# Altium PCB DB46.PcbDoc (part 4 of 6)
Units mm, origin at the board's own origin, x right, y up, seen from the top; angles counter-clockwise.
Board outline 82.2 x 113.2 mm, 8 copper layers (Top Layer, MidLayer1, MidLayer2, GND, MidLayer3, VCC, MidLayer4, Bottom Layer), stack 1.576 mm thick; 186 components, 477 nets, 1727 pads, 1538 vias.
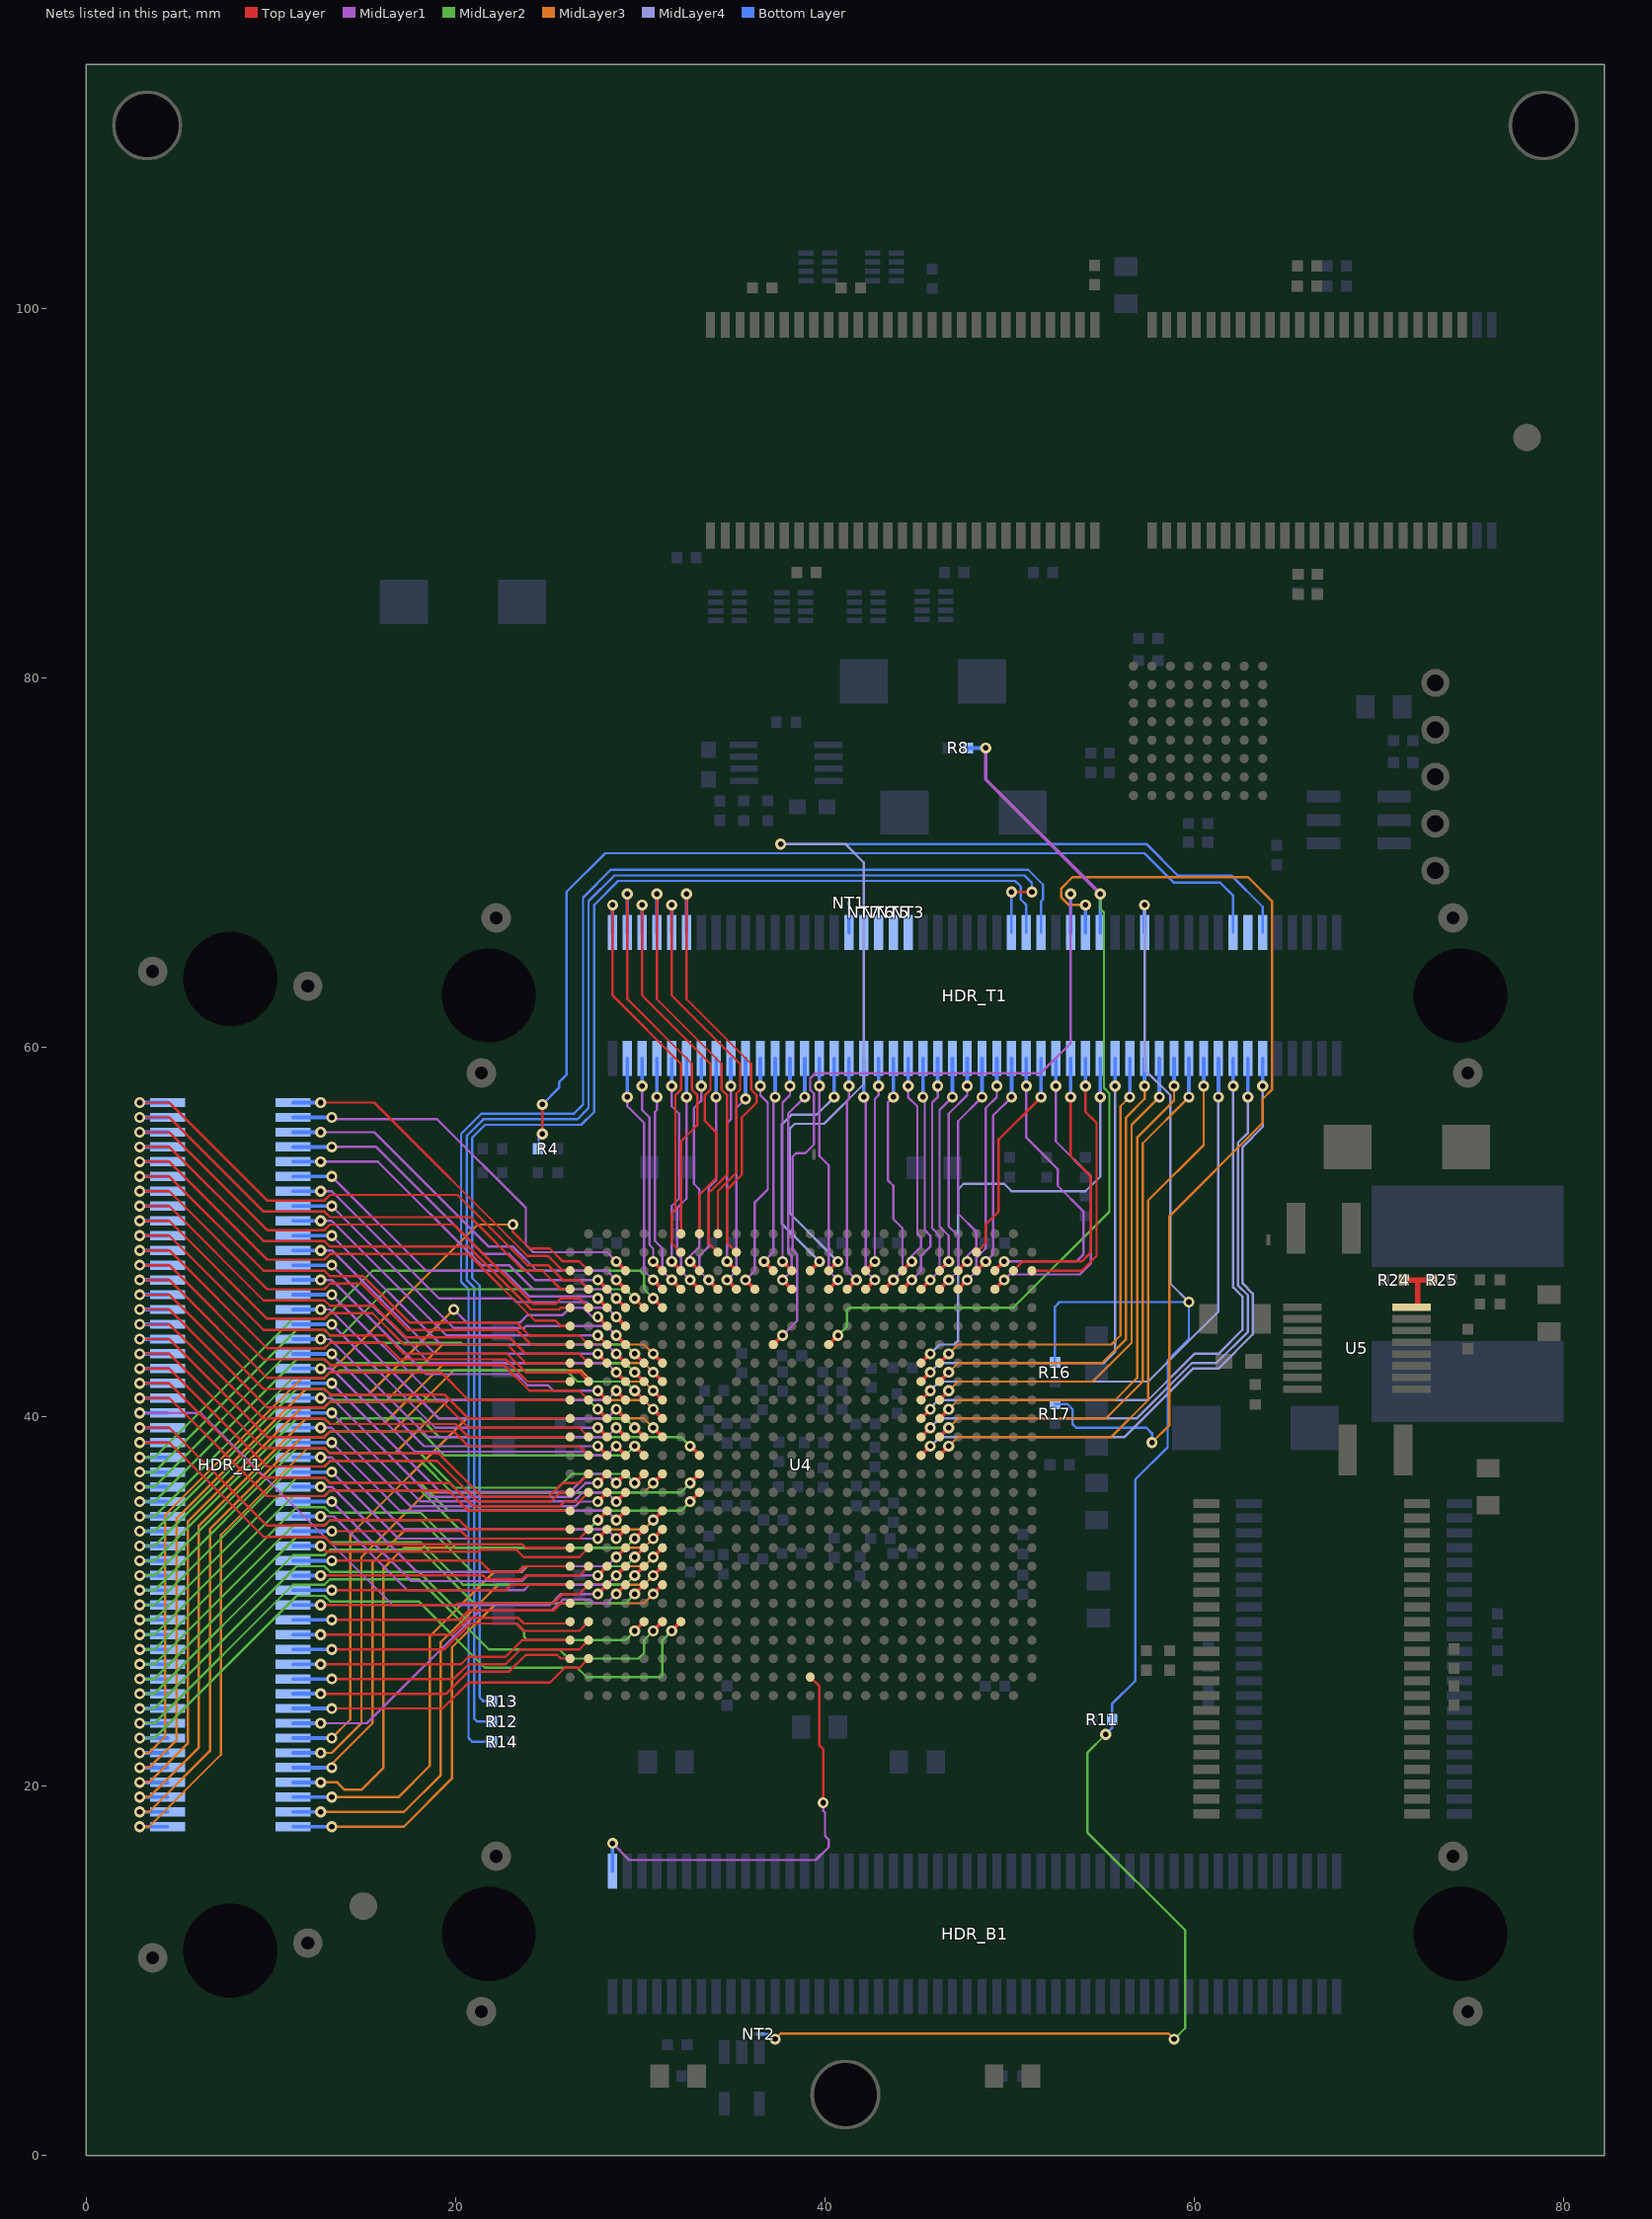
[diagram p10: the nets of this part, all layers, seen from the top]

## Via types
v1: diameter 0.6, hole 0.3, Top Layer to Bottom Layer, 904 vias
v2: diameter 0.6, hole 0.3, Top Layer to Bottom Layer, tented both sides, 506 vias
v3: diameter 0.7, hole 0.4, Top Layer to Bottom Layer, 127 vias
v4: diameter 0.6, hole 0.3, Top Layer to Bottom Layer, tented top, 1 vias

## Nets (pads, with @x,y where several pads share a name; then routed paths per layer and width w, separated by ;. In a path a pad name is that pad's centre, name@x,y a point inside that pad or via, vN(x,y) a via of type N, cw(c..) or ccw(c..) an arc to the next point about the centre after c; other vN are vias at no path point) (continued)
EXTEND_A0: HDR_L1.1 U4.D2 | length 30.2
  Top Layer w0.127: v2(2.9,57) 4.5,57 9.8,51.7 12.9,51.7 13.2,52 20.1,52 23.9,48.2 24.3,48.2 24.6,48.2 25,48.2 25.8,47.4 26.7,47.4 U4.D2@27.2,46.9
  Bottom Layer w0.2: v2(2.9,57) HDR_L1.1@4.4,57
EXTEND_A1: HDR_L1.3 U4.D1 | length 29.1
  Top Layer w0.127: v2(2.9,56.2) 3.9,56.2 ; 3.5,56.2 4.5,56.2 9.6,51.1 12.9,51.1 13.2,50.8 20.8,50.8 23.7,47.9 24.3,47.9 24.6,47.9 24.7,47.9 25.7,46.9 U4.D1@26.2,46.9
  Bottom Layer w0.2: v2(2.9,56.2) HDR_L1.3@4.4,56.2
EXTEND_A2: HDR_L1.5 U4.E2 | length 30.7
  Top Layer w0.127: v2(2.9,55.4) 4,55.4 ; 3.5,55.4 4.5,55.4 9.8,50.1 12.9,50.1 13.2,50.4 19.9,50.4 24.2,46.1 24.3,46.1 24.6,46.1 25.4,46.1 25.7,46.4 26.7,46.4 U4.E2@27.2,45.9
  Bottom Layer w0.2: v2(2.9,55.4) HDR_L1.5@4.4,55.4
EXTEND_A3: HDR_L1.7 U4.E1 | length 28.9
  Top Layer w0.127: v2(2.9,54.6) 3.9,54.6 ; 3.5,54.6 4.5,54.6 9.6,49.5 12.9,49.5 13.2,49.2 20.7,49.2 24.1,45.8 24.3,45.8 24.6,45.8 25.6,45.8 25.7,45.9 U4.E1@26.2,45.9
  Bottom Layer w0.2: v2(2.9,54.6) HDR_L1.7@4.4,54.6
EXTEND_A4: HDR_L1.9 U4.F1 | length 29
  Top Layer w0.127: v2(2.9,53.8) 3.8,53.8 ; 3.5,53.8 4.5,53.8 9.8,48.5 12.9,48.5 13.2,48.8 20.7,48.8 24.3,45.2 24.6,45.2 25.4,45.2 25.7,44.9 U4.F1@26.2,44.9
  Bottom Layer w0.2: v2(2.9,53.8) HDR_L1.9@4.4,53.8
EXTEND_A5: HDR_L1.11 U4.G2 | length 29.9
  Top Layer w0.127: v2(2.9,53) 3.8,53 ; 3.5,53 4.5,53 9.6,47.9 12.9,47.9 13.2,47.6 15,47.6 17.5,45.1 23.3,45.1 23.5,44.9 24,44.4 25.8,44.4 26.7,44.4 U4.G2@27.2,43.9
  Bottom Layer w0.2: v2(2.9,53) HDR_L1.11@4.4,53
EXTEND_A6: HDR_L1.13 U4.G1 | length 28.8
  Top Layer w0.127: v2(2.9,52.2) 3.8,52.2 ; 3.5,52.2 4.5,52.2 9.8,46.9 12.9,46.9 13.2,47.2 14.9,47.2 17.4,44.7 23.3,44.7 24.1,43.9 24.3,43.9 24.6,43.9 U4.G1@26.2,43.9
  Bottom Layer w0.2: v2(2.9,52.2) HDR_L1.13@4.4,52.2
EXTEND_A7: HDR_L1.15 U4.H2 | length 29.6
  Top Layer w0.127: v2(2.9,51.4) 3.8,51.4 ; 3.5,51.4 4.5,51.4 9.6,46.3 12.9,46.3 13.2,46 15.6,46 17.3,44.3 22.9,44.3 23.8,43.4 24.3,43.4 24.6,43.4 26.7,43.4 U4.H2@27.2,42.9
  Bottom Layer w0.2: v2(2.9,51.4) HDR_L1.15@4.4,51.4
EXTEND_A8: HDR_L1.17 U4.H1 | length 28.5
  Top Layer w0.127: v2(2.9,50.6) 3.8,50.6 ; 3.5,50.6 4.5,50.6 9.8,45.3 12.9,45.3 13.2,45.6 15.5,45.6 17.2,43.9 22.8,43.9 23.8,42.9 24.3,42.9 24.6,42.9 U4.H1@26.2,42.9
  Bottom Layer w0.2: v2(2.9,50.6) HDR_L1.17@4.4,50.6
EXTEND_A9: HDR_L1.19 U4.J2 | length 29.4
  Top Layer w0.127: v2(2.9,49.8) 3.8,49.8 ; 3.5,49.8 4.5,49.8 9.6,44.7 12.9,44.7 13.2,44.4 16.2,44.4 17.2,43.4 22.8,43.4 23.8,42.4 24.3,42.4 24.6,42.4 26.7,42.4 U4.J2@27.2,41.9
  Bottom Layer w0.2: v2(2.9,49.8) HDR_L1.19@4.4,49.8
EXTEND_A10: HDR_L1.21 U4.J1 | length 28.3
  Top Layer w0.127: v2(2.9,49) 3.8,49 ; 3.5,49 4.5,49 9.8,43.7 12.9,43.7 13.2,44 16.1,44 17,43.1 22.7,43.1 23.9,41.9 24.3,41.9 24.6,41.9 U4.J1@26.2,41.9
  Bottom Layer w0.2: v2(2.9,49) HDR_L1.21@4.4,49
EXTEND_A11: HDR_L1.23 U4.K2 | length 29.1
  Top Layer w0.127: v2(2.9,48.2) 3.8,48.2 ; 3.5,48.2 4.5,48.2 9.6,43.1 12.9,43.1 13.2,42.8 22.6,42.8 24,41.4 24.3,41.4 24.6,41.4 26.7,41.4 U4.K2@27.2,40.9
  Bottom Layer w0.2: v2(2.9,48.2) HDR_L1.23@4.4,48.2
EXTEND_A12: HDR_L1.25 U4.K1 | length 27.7
  Top Layer w0.127: v2(2.9,47.4) 4.5,47.4 9.8,42.1 12.9,42.1 13.2,42.4 19.2,42.4 20.7,40.9 24.3,40.9 24.6,40.9 U4.K1@26.2,40.9
  Bottom Layer w0.2: v2(2.9,47.4) HDR_L1.25@4.4,47.4
EXTEND_A13: HDR_L1.27 U4.L1 | length 27.6
  Top Layer w0.127: v2(2.9,46.6) 4.5,46.6 9.6,41.5 12.9,41.5 13.2,41.2 19.4,41.2 20.7,39.9 24.3,39.9 24.6,39.9 U4.L1@26.2,39.9
  Bottom Layer w0.2: v2(2.9,46.6) HDR_L1.27@4.4,46.6
EXTEND_A14: HDR_L1.29 U4.M2 | length 28.9
  Top Layer w0.127: v2(2.9,45.8) 4.5,45.8 9.8,40.5 12.9,40.5 13.2,40.8 19.3,40.8 20.7,39.4 24.3,39.4 24.6,39.4 26.7,39.4 U4.M2@27.2,38.9
  Bottom Layer w0.2: v2(2.9,45.8) HDR_L1.29@4.4,45.8
EXTEND_A15: HDR_L1.31 U4.M1 | length 27.3
  Top Layer w0.127: v2(2.9,45) 4.5,45 9.6,39.9 12.9,39.9 13.2,39.6 20,39.6 20.7,38.9 24.3,38.9 24.6,38.9 U4.M1@26.2,38.9
  Bottom Layer w0.2: v2(2.9,45) HDR_L1.31@4.4,45
EXTEND_A16: HDR_L1.33 U4.N2 | length 28.7
  Top Layer w0.127: v2(2.9,44.2) 4.5,44.2 9.8,38.9 12.9,38.9 13.2,39.2 19.9,39.2 20.7,38.4 24.3,38.4 24.6,38.4 26.7,38.4 U4.N2@27.2,37.9
  Bottom Layer w0.2: v2(2.9,44.2) HDR_L1.33@4.4,44.2
EXTEND_A17: HDR_L1.35 U4.P2 | length 29.5
  Top Layer w0.127: v2(2.9,43.4) 4.5,43.4 9.6,38.3 12.9,38.3 13.2,38 19.1,38 21.438,35.662 25.046,35.662 25.784,36.4 26.7,36.4 U4.P2@27.2,36.9
  Bottom Layer w0.2: v2(2.9,43.4) HDR_L1.35@4.4,43.4
EXTEND_A18: HDR_L1.37 U4.R1 | length 28.2
  Top Layer w0.127: v2(2.9,42.6) 4.5,42.6 9.8,37.3 12.9,37.3 13.2,37.6 19,37.6 20.7,35.9 21.192,35.408 25.151,35.408 25.643,35.9 U4.R1@26.2,35.9
  Bottom Layer w0.2: v2(2.9,42.6) HDR_L1.37@4.4,42.6
EXTEND_A19: HDR_L1.39 U4.R2 | length 28.9
  Top Layer w0.127: v2(2.9,41.8) 4.5,41.8 9.6,36.7 12.9,36.7 13.2,36.4 19.7,36.4 20.946,35.154 25.654,35.154 25.9,35.4 26.7,35.4 U4.R2@27.2,35.9
  Bottom Layer w0.2: v2(2.9,41.8) HDR_L1.39@4.4,41.8
EXTEND_A20: HDR_L1.41 U4.T1 | length 27.6
  Top Layer w0.127: v2(2.9,41) 4.5,41 9.8,35.7 12.9,35.7 13.2,36 19.6,36 20.7,34.9 24.3,34.9 24.6,34.9 U4.T1@26.2,34.9
  Bottom Layer w0.2: v2(2.9,41) HDR_L1.41@4.4,41
EXTEND_A21: HDR_L1.43 U4.Y3 | length 31.6
  Top Layer w0.2: v1(27.7,30.4) U4.Y3@28.2,30.9
  MidLayer1 w0.127: v2(2.9,40.2) 6.2,40.2 16.6,29.8 24.3,29.8 24.6,29.8 25.1,29.8 25.7,30.4 v1(27.7,30.4)
  Bottom Layer w0.2: v2(2.9,40.2) HDR_L1.43@4.4,40.2
EXTEND_A22: HDR_L1.45 U4.U1 | length 27.3
  Top Layer w0.127: v2(2.9,39.4) 4.5,39.4 9.8,34.1 12.9,34.1 13.2,34.4 20.2,34.4 20.7,33.9 24.3,33.9 24.6,33.9 U4.U1@26.2,33.9
  Bottom Layer w0.2: v2(2.9,39.4) HDR_L1.45@4.4,39.4
EXTEND_A23: HDR_L1.47 U4.V1 | length 27.5
  Top Layer w0.127: v2(2.9,38.6) 3.8,38.6 ; 3.5,38.6 4.5,38.6 9.6,33.5 12.9,33.5 13.3,33.1 23.6,33.1 23.8,32.9 24.3,32.9 24.6,32.9 U4.V1@26.2,32.9
  Bottom Layer w0.2: v2(2.9,38.6) HDR_L1.47@4.4,38.6
EXTEND_A24: HDR_L1.49 U4.E6 | length 35.3
  Top Layer w0.2: v1(30.7,46.4) U4.E6@31.2,45.9
  MidLayer2 w0.127: v2(2.9,37.8) 3.7,37.8 11.2,45.3 12.9,45.3 14,46.4 15.5,47.9 24.3,47.9 24.6,47.9 30,47.9 30.2,47.7 30.2,46.9 v1(30.7,46.4)
  Bottom Layer w0.2: v2(2.9,37.8) HDR_L1.49@4.4,37.8
EXTEND_A25: HDR_L1.51 U4.E5 | length 33.6
  Top Layer w0.2: v1(29.7,46.4) U4.E5@30.2,45.9
  MidLayer2 w0.127: v2(2.9,37) 3.7,37 11.4,44.7 12.9,44.7 13.2,44.4 13.8,44.4 15.4,46 16.3,46.9 24.3,46.9 24.6,46.9 29.2,46.9 v1(29.7,46.4)
  Bottom Layer w0.2: v2(2.9,37) HDR_L1.51@4.4,37
EXTEND_A26: HDR_L1.53 U4.H5 | length 32.5
  Top Layer w0.2: v1(29.7,43.4) U4.H5@30.2,42.9
  MidLayer2 w0.127: v2(2.9,36.2) 3.7,36.2 11.2,43.7 12.9,43.7 13.2,44 20.3,44 20.4,43.9 24.3,43.9 24.6,43.9 29.2,43.9 v1(29.7,43.4)
  Bottom Layer w0.2: v2(2.9,36.2) HDR_L1.53@4.4,36.2
EXTEND_A27: HDR_L1.55 U4.J5 | length 32.6
  Top Layer w0.2: v1(29.7,42.4) U4.J5@30.2,41.9
  MidLayer2 w0.127: v2(2.9,35.4) 3.7,35.4 11.4,43.1 12.9,43.1 13.2,42.8 13.5,42.8 13.6,42.9 24.3,42.9 24.6,42.9 29.2,42.9 v1(29.7,42.4)
  Bottom Layer w0.2: v2(2.9,35.4) HDR_L1.55@4.4,35.4
EXTEND_A28: HDR_L1.57 U4.K5 | length 32.7
  Top Layer w0.2: v1(29.7,41.4) U4.K5@30.2,40.9
  MidLayer2 w0.127: v2(2.9,34.6) 3.7,34.6 11.2,42.1 12.9,42.1 13.2,42.4 13.6,42.4 13.7,42.5 24.3,42.5 24.6,42.5 26,42.5 26.6,41.9 29.2,41.9 v1(29.7,41.4)
  Bottom Layer w0.2: v2(2.9,34.6) HDR_L1.57@4.4,34.6
EXTEND_A29: HDR_L1.59 U4.L3 | length 30.8
  Top Layer w0.2: v1(27.7,40.4) U4.L3@28.2,39.9
  MidLayer2 w0.127: v2(2.9,33.8) 3.7,33.8 11.4,41.5 12.9,41.5 13.2,41.2 18.2,41.2 18.5,40.9 24.3,40.9 24.6,40.9 27.2,40.9 v1(27.7,40.4)
  Bottom Layer w0.2: v2(2.9,33.8) HDR_L1.59@4.4,33.8
  Bottom Layer w0.381: v1(27.7,40.4) v1@27.7,40.508
EXTEND_A30: HDR_L1.61 U4.M5 | length 32.9
  Top Layer w0.2: v1(29.7,39.4) U4.M5@30.2,38.9
  MidLayer2 w0.127: v2(2.9,33) 3.7,33 11.2,40.5 12.9,40.5 13.3,40.9 18.1,40.9 19.1,39.9 24.3,39.9 24.6,39.9 29.2,39.9 v1(29.7,39.4)
  Bottom Layer w0.2: v2(2.9,33) HDR_L1.61@4.4,33
EXTEND_A31: HDR_L1.63 U4.N8 | length 36.1
  Top Layer w0.2: v1@32.7,38.475 32.737,38.432 U4.N8@33.2,37.9
  MidLayer2 w0.127: v2(2.9,32.2) 3.7,32.2 11.4,39.9 12.9,39.9 13.2,39.6 13.5,39.6 13.8,39.9 18.1,39.9 19.1,38.9 24.3,38.9 24.6,38.9 32.2,38.9 v1(32.7,38.4)
  Bottom Layer w0.2: v2(2.9,32.2) HDR_L1.63@4.4,32.2
EXTEND_A32: HDR_L1.65 U4.N5 | length 33
  Top Layer w0.2: v1(29.7,38.4) U4.N5@30.2,37.9
  MidLayer2 w0.127: v2(2.9,31.4) 3.7,31.4 11.2,38.9 12.9,38.9 13.2,39.2 18.1,39.2 19.4,37.9 24.3,37.9 24.6,37.9 29.2,37.9 v1(29.7,38.4)
  Bottom Layer w0.2: v2(2.9,31.4) HDR_L1.65@4.4,31.4
EXTEND_A33: HDR_L1.67 U4.P5 | length 33.6
  Top Layer w0.2: v1(29.7,36.4) U4.P5@30.2,36.9
  MidLayer2 w0.127: v2(2.9,30.6) 3.7,30.6 11.4,38.3 12.9,38.3 13.2,38 18.1,38 19.946,36.154 25.554,36.154 26.3,36.9 29.2,36.9 v1(29.7,36.4)
  Bottom Layer w0.2: v2(2.9,30.6) HDR_L1.67@4.4,30.6
EXTEND_A34: HDR_L1.69 U4.P8 | length 36.1
  Top Layer w0.2: v1(32.7,36.4) U4.P8@33.2,36.9
  MidLayer2 w0.127: v2(2.9,29.8) 3.7,29.8 11.2,37.3 12.9,37.3 13.2,37.6 18.1,37.6 19.8,35.9 24.3,35.9 24.6,35.9 32.2,35.9 v1(32.7,36.4)
  Bottom Layer w0.2: v2(2.9,29.8) HDR_L1.69@4.4,29.8
EXTEND_A35: HDR_L1.71 U4.R8 | length 36.1
  Top Layer w0.2: v1(32.7,35.4) U4.R8@33.2,35.9
  MidLayer2 w0.127: v2(2.9,29) 3.7,29 11.4,36.7 12.9,36.7 13.2,36.4 18.1,36.4 19.6,34.9 24.3,34.9 24.6,34.9 32.2,34.9 v1(32.7,35.4)
  Bottom Layer w0.2: v2(2.9,29) HDR_L1.71@4.4,29
EXTEND_A36: HDR_L1.73 U4.T3 | length 31.4
  Top Layer w0.2: v1(27.7,34.4) U4.T3@28.2,34.9
  MidLayer2 w0.127: v2(2.9,28.2) 3.7,28.2 11.2,35.7 12.9,35.7 13.2,36 18.1,36 20.2,33.9 24.3,33.9 24.6,33.9 27.2,33.9 v1(27.7,34.4)
  Bottom Layer w0.2: v2(2.9,28.2) HDR_L1.73@4.4,28.2
  Bottom Layer w0.381: v1(27.7,34.4) v1@27.7,34.508
EXTEND_A37: HDR_L1.75 U4.U5 | length 33.3
  Top Layer w0.2: v1(29.7,33.4) U4.U5@30.2,33.9
  MidLayer2 w0.127: v2(2.9,27.4) 3.7,27.4 11.4,35.1 12.9,35.1 13.2,34.8 18.1,34.8 20,32.9 24.3,32.9 24.6,32.9 29.2,32.9 v1(29.7,33.4)
  Bottom Layer w0.2: v2(2.9,27.4) HDR_L1.75@4.4,27.4
EXTEND_A38: HDR_L1.77 U4.V5 | length 33.7
  Top Layer w0.2: v1(29.7,32.4) U4.V5@30.2,32.9
  MidLayer2 w0.127: v2(2.9,26.6) 3.7,26.6 11.2,34.1 12.9,34.1 13.2,34.4 18.1,34.4 20.9,31.6 23.4,31.6 23.7,31.9 24.3,31.9 24.6,31.9 29.2,31.9 v1(29.7,32.4)
  Bottom Layer w0.2: v2(2.9,26.6) HDR_L1.77@4.4,26.6
EXTEND_A39: HDR_L1.79 U4.W5 | length 33.5
  Top Layer w0.2: v1(29.7,31.4) U4.W5@30.2,31.9
  MidLayer2 w0.127: v2(2.9,25.8) 3.7,25.8 11.4,33.5 12.9,33.5 13.2,33.2 18.1,33.2 20.4,30.9 24.3,30.9 24.6,30.9 29.2,30.9 v1(29.7,31.4)
  Bottom Layer w0.2: v2(2.9,25.8) HDR_L1.79@4.4,25.8
EXTEND_A40: HDR_L1.81 U4.Y5 | length 33.6
  Top Layer w0.2: v1(29.7,30.4) U4.Y5@30.2,30.9
  MidLayer2 w0.127: v2(2.9,25) 3.7,25 11.2,32.5 12.9,32.5 13.2,32.8 18.1,32.8 21,29.9 24.3,29.9 24.6,29.9 29.2,29.9 v1(29.7,30.4)
  Bottom Layer w0.2: v2(2.9,25) HDR_L1.81@4.4,25
EXTEND_A41: HDR_L1.83 U4.AB5 | length 34.2
  Top Layer w0.2: v1(29.7,28.4) U4.AB5@30.2,28.9
  MidLayer2 w0.127: v2(2.9,24.2) 3.7,24.2 11.4,31.9 12.9,31.9 13.2,31.6 18,31.6 20.8,28.8 23.3,28.8 23.7,28.4 23.7,28.1 23.9,27.9 24.3,27.9 24.6,27.9 29.2,27.9 v1(29.7,28.4)
  Bottom Layer w0.2: v2(2.9,24.2) HDR_L1.83@4.4,24.2
EXTEND_A42: HDR_L1.85 U4.AB6 | length 36.1
  Top Layer w0.2: v1(30.7,28.4) U4.AB6@31.2,28.9
  MidLayer2 w0.127: v2(2.9,23.4) 3.7,23.4 11.2,30.9 12.9,30.9 13.2,31.2 18,31.2 21.8,27.4 24.3,27.4 24.6,27.4 25.625,27.4 26.125,26.9 29.9,26.9 30.2,27.2 30.2,27.9 v1(30.7,28.4)
  Bottom Layer w0.2: v2(2.9,23.4) HDR_L1.85@4.4,23.4
EXTEND_A43: HDR_L1.87 U4.AB7 | length 38.2
  Top Layer w0.2: v1(31.7,28.4) U4.AB7@32.2,28.9
  MidLayer2 w0.127: v2(2.9,22.6) 3.7,22.6 11.4,30.3 12.9,30.3 13.2,30 18,30 21.6,26.4 24.3,26.4 24.6,26.4 26.6,26.4 27.1,25.9 31.1,25.9 31.2,26 31.2,27.9 v1(31.7,28.4)
  Bottom Layer w0.2: v2(2.9,22.6) HDR_L1.87@4.4,22.6
EXTEND_A44: HDR_L1.89 U4.C2 | length 45.9
  Top Layer w0.127: v1(23.1,50.4) 23.1,50 24,49.1 24.3,49.1 24.6,49.1 25.1,49.1 25.8,48.4 26.7,48.4 U4.C2@27.2,47.9
  MidLayer3 w0.127: v2(2.9,21.8) 3.4,21.8 4.277,22.677 4.277,34.677 11.7,42.1 12.9,42.1 21.2,50.4 v1(23.1,50.4)
  Bottom Layer w0.2: v2(2.9,21.8) HDR_L1.89@4.4,21.8
EXTEND_A45: HDR_L1.91 U4.F3 | length 45.4
  Top Layer w0.2: v1(27.7,45.4) U4.F3@28.2,44.9
  MidLayer1 w0.127: v1(19.9,45.8) 20.6,45.1 23.5,45.1 23.9,45.5 24.3,45.5 24.6,45.5 25.8,45.5 26.2,45.9 26.9,45.9 27.4,45.4 v1(27.7,45.4)
  MidLayer3 w0.127: v2(2.9,21) 3.4,21 4.9,22.5 4.9,34.5 11.9,41.5 12.9,41.5 13.2,41.2 15.3,41.2 v1(19.9,45.8)
  Bottom Layer w0.2: v2(2.9,21) HDR_L1.91@4.4,21
EXTEND_A46: HDR_L1.93 U4.H6 | length 47.1
  Top Layer w0.2: v1(30.7,43.4) U4.H6@31.2,42.9
  MidLayer3 w0.127: v2(2.9,20.2) 3.4,20.2 5.5,22.3 5.5,34.3 11.7,40.5 12.9,40.5 13.2,40.8 16.2,40.8 19.3,43.9 24.3,43.9 24.6,43.9 30.2,43.9 v1(30.7,43.4)
  Bottom Layer w0.2: v2(2.9,20.2) HDR_L1.93@4.4,20.2
EXTEND_A47: HDR_L1.95 U4.J6 | length 47.2
  Top Layer w0.2: v1(30.7,42.4) U4.J6@31.2,41.9
  MidLayer3 w0.127: v2(2.9,19.4) 3.4,19.4 6.1,22.1 6.1,34.1 11.9,39.9 12.9,39.9 13.2,39.6 16.1,39.6 19.4,42.9 24.3,42.9 24.6,42.9 30.2,42.9 v1(30.7,42.4)
  Bottom Layer w0.2: v2@2.9,19.4 HDR_L1.95@4.4,19.4
EXTEND_A48: HDR_L1.97 U4.K6 | length 47.4
  Top Layer w0.2: v1(30.7,41.4) U4.K6@31.2,40.9
  MidLayer3 w0.127: v2(2.9,18.6) 3.4,18.6 6.7,21.9 6.7,33.9 11.7,38.9 12.912,38.9 12.912,38.912 13.2,39.2 16.6,39.2 19.9,42.5 24.3,42.5 24.6,42.5 26.8,42.5 27.4,41.9 30.2,41.9 v1(30.7,41.4)
  Bottom Layer w0.2: v2(2.9,18.6) HDR_L1.97@4.4,18.6
EXTEND_A49: HDR_L1.99 U4.L6 | length 47
  Top Layer w0.2: v1(30.7,40.4) U4.L6@31.2,39.9
  MidLayer3 w0.127: v2(2.9,17.8) 3.4,17.8 7.3,21.7 7.3,33.6 12,38.3 12.9,38.3 13.2,38 16.7,38 19.6,40.9 24.3,40.9 24.6,40.9 30.2,40.9 v1(30.7,40.4)
  Bottom Layer w0.2: v2(2.9,17.8) HDR_L1.99@4.4,17.8
EXTEND_B0: HDR_L1.2 U4.C1 | length 18.8
  Top Layer w0.127: v2(12.7,57) 15.6,57 23.9,48.7 24.3,48.7 24.6,48.7 25,48.7 25.8,47.9 U4.C1@26.2,47.9
  Bottom Layer w0.2: HDR_L1.2@11.2,57 v2(12.7,57)
EXTEND_B1: HDR_L1.4 U4.C4 | length 22.6
  Top Layer w0.2: v1(28.7,48.4) U4.C4@29.2,47.9
  MidLayer1 w0.127: v2(13.3,56.2) 13.4,56.2 13.5,56.1 19,56.1 23.8,51.3 23.8,49.3 24.2,48.9 28.2,48.9 v1(28.7,48.4)
  Bottom Layer w0.2: HDR_L1.4@11.2,56.2 v2(13.3,56.2)
EXTEND_B2: HDR_L1.6 U4.D4 | length 21.5
  Top Layer w0.2: v1(28.7,47.4) U4.D4@29.2,46.9
  MidLayer1 w0.127: v2(12.7,55.4) 15.6,55.4 21.8,49.2 23.1,49.2 24.4,47.9 28.2,47.9 v1(28.7,47.4)
  Bottom Layer w0.2: HDR_L1.6@11.2,55.4 v2(12.7,55.4)
EXTEND_B3: HDR_L1.8 U4.D3 | length 20.2
  Top Layer w0.2: v1(27.7,47.4) U4.D3@28.2,46.9
  MidLayer1 w0.127: v2(13.3,54.6) 15.7,54.6 21.5,48.8 22.9,48.8 24.3,47.4 v1(27.7,47.4)
  Bottom Layer w0.2: HDR_L1.8@11.2,54.6 v2(13.3,54.6)
EXTEND_B4: HDR_L1.10 U4.E4 | length 21.3
  Top Layer w0.2: v1(28.7,46.4) U4.E4@29.2,45.9
  MidLayer1 w0.127: v2(12.7,53.8) 15.8,53.8 21.4,48.2 22.9,48.2 24.2,46.9 28.2,46.9 v1(28.7,46.4)
  Bottom Layer w0.2: HDR_L1.10@11.2,53.8 v2(12.7,53.8)
EXTEND_B5: HDR_L1.12 U4.E3 | length 19.9
  Top Layer w0.2: v1(27.7,46.4) U4.E3@28.2,45.9
  MidLayer1 w0.127: v2(13.3,53) 18.4,47.9 22.6,47.9 24,46.5 27.6,46.5 v1(27.7,46.4)
  Bottom Layer w0.2: HDR_L1.12@11.2,53 v2(13.3,53)
EXTEND_B6: HDR_L1.14 U4.F4 | length 21
  Top Layer w0.2: v1(28.7,45.4) U4.F4@29.2,44.9
  MidLayer1 w0.127: v2(12.7,52.2) 13.3,52.2 19.1,46.4 23.1,46.4 23.3,46.2 24.3,46.2 24.6,46.2 27.1,46.2 27.4,45.9 28.2,45.9 v1(28.7,45.4)
  Bottom Layer w0.2: HDR_L1.14@11.2,52.2 v2(12.7,52.2)
EXTEND_B7: HDR_L1.16 U4.G4 | length 21.2
  Top Layer w0.2: v1(28.7,44.4) U4.G4@29.2,43.9
  MidLayer1 w0.127: v2(13.3,51.4) 19.9,44.8 23.7,44.8 23.8,44.9 24.3,44.9 24.6,44.9 28.2,44.9 v1(28.7,44.4)
  Bottom Layer w0.2: HDR_L1.16@11.2,51.4 v2(13.3,51.4)
EXTEND_B8: HDR_L1.18 U4.G3 | length 19.8
  Top Layer w0.127: v1(27.7,44.4) U4.G3@28.2,43.9
  MidLayer1 w0.127: v2(12.7,50.6) 13.3,50.6 19.5,44.4 24.3,44.4 24.6,44.4 v1(27.7,44.4)
  Bottom Layer w0.2: HDR_L1.18@11.2,50.6 v2(12.7,50.6)
EXTEND_B9: HDR_L1.20 U4.H4 | length 23.8
  Top Layer w0.2: v1(28.7,43.4) U4.H4@29.2,42.9
  MidLayer1 w0.127: v2(13.3,49.8) 19.2,43.9 24.3,43.9 24.6,43.9 28.2,43.9 ; 25.3,43.9 28.2,43.9 ; v1(28.7,43.4) 28.2,43.9
  Bottom Layer w0.2: HDR_L1.20@11.2,49.8 v2(13.3,49.8)
EXTEND_B10: HDR_L1.22 U4.H3 | length 19.5
  Top Layer w0.2: v1(27.7,43.4) U4.H3@28.2,42.9
  MidLayer1 w0.127: v2(12.7,49) 13.3,49 18.9,43.4 24.3,43.4 24.6,43.4 v1(27.7,43.4)
  Bottom Layer w0.2: HDR_L1.22@11.2,49 v2(12.7,49)
EXTEND_B11: HDR_L1.24 U4.J4 | length 20.6
  Top Layer w0.2: v1(28.7,42.4) U4.J4@29.2,41.9
  MidLayer1 w0.127: v2(13.3,48.2) 18.6,42.9 24.3,42.9 24.6,42.9 28.2,42.9 v1(28.7,42.4)
  Bottom Layer w0.2: HDR_L1.24@11.2,48.2 v2(13.3,48.2)
EXTEND_B12: HDR_L1.26 U4.K3 | length 19.7
  Top Layer w0.2: v1(27.7,41.4) U4.K3@28.2,40.9
  MidLayer1 w0.127: v2(12.7,47.4) 13.3,47.4 18.4,42.3 23.3,42.3 23.9,41.7 24.3,41.7 24.6,41.7 25,41.7 25.3,41.4 v1(27.7,41.4)
  Bottom Layer w0.2: HDR_L1.26@11.2,47.4 v2(12.7,47.4)
EXTEND_B13: HDR_L1.28 U4.K4 | length 20.8
  Top Layer w0.2: v1(28.7,41.4) U4.K4@29.2,40.9
  MidLayer1 w0.127: v2(13.3,46.6) 19,40.9 24.3,40.9 24.6,40.9 25.3,40.9 28.2,40.9 v1(28.7,41.4)
  Bottom Layer w0.2: HDR_L1.28@11.2,46.6 v2(13.3,46.6)
EXTEND_B14: HDR_L1.30 U4.L4 | length 20.9
  Top Layer w0.2: v1(28.7,40.4) U4.L4@29.2,39.9
  MidLayer1 w0.127: v2(12.7,45.8) 13.2,45.8 19.1,39.9 24.3,39.9 24.6,39.9 28.2,39.9 v1(28.7,40.4)
  Bottom Layer w0.2: HDR_L1.30@11.2,45.8 v2(12.7,45.8)
EXTEND_B15: HDR_L1.32 U4.M3 | length 19.5
  Top Layer w0.2: v1(27.7,39.4) U4.M3@28.2,38.9
  MidLayer1 w0.127: v2(13.3,45) 18.9,39.4 24.3,39.4 24.6,39.4 v1(27.7,39.4)
  Bottom Layer w0.2: HDR_L1.32@11.2,45 v2(13.3,45)
EXTEND_B16: HDR_L1.34 U4.M4 | length 20.6
  Top Layer w0.2: v1(28.7,39.4) U4.M4@29.2,38.9
  MidLayer1 w0.127: v2(12.7,44.2) 13.2,44.2 18.5,38.9 24.3,38.9 24.6,38.9 28.2,38.9 v1(28.7,39.4)
  Bottom Layer w0.2: HDR_L1.34@11.2,44.2 v2(12.7,44.2)
EXTEND_B17: HDR_L1.36 U4.N3 | length 19.3
  Top Layer w0.2: v1(27.7,38.4) U4.N3@28.2,37.9
  MidLayer1 w0.127: v2(13.3,43.4) 18.3,38.4 24.3,38.4 24.6,38.4 v1(27.7,38.4)
  Bottom Layer w0.2: HDR_L1.36@11.2,43.4 v2(13.3,43.4)
EXTEND_B18: HDR_L1.38 U4.N4 | length 20.4
  Top Layer w0.2: v1(28.7,38.4) U4.N4@29.2,37.9
  MidLayer1 w0.127: v2(12.7,42.6) 13.3,42.6 17.8,38.1 24.3,38.1 24.6,38.1 27.2,38.1 27.4,37.9 28.2,37.9 v1(28.7,38.4)
  Bottom Layer w0.2: HDR_L1.38@11.2,42.6 v2(12.7,42.6)
EXTEND_B19: HDR_L1.40 U4.P4 | length 21.3
  Top Layer w0.2: v1(28.7,36.4) U4.P4@29.2,36.9
  MidLayer1 w0.127: v2(13.3,41.8) 19.184,35.916 26.184,35.916 27.168,36.9 28.2,36.9 v1(28.7,36.4)
  Bottom Layer w0.2: HDR_L1.40@11.2,41.8 v2(13.3,41.8)
EXTEND_B20: HDR_L1.42 U4.P3 | length 19.7
  Top Layer w0.2: v1(27.7,36.4) U4.P3@28.2,36.9
  MidLayer1 w0.127: v2(12.7,41) 13.3,41 18.638,35.662 26.29,35.662 27.027,36.4 v1(27.7,36.4)
  Bottom Layer w0.2: HDR_L1.42@11.2,41 v2(12.7,41)
EXTEND_B21: HDR_L1.44 U4.R4 | length 20.6
  Top Layer w0.2: v1(28.7,35.4) U4.R4@29.2,35.9
  MidLayer1 w0.127: v2(13.3,40.2) 18.092,35.408 26.395,35.408 26.887,35.9 28.2,35.9 v1(28.7,35.4)
  Bottom Layer w0.2: HDR_L1.44@11.2,40.2 v2(13.3,40.2)
EXTEND_B22: HDR_L1.46 U4.R3 | length 19.1
  Top Layer w0.2: v1(27.7,35.4) U4.R3@28.2,35.9
  MidLayer1 w0.127: v2(12.7,39.4) 13.3,39.4 17.546,35.154 26.5,35.154 26.746,35.4 v1(27.7,35.4)
  Bottom Layer w0.2: HDR_L1.46@11.2,39.4 v2(12.7,39.4)
EXTEND_B23: HDR_L1.48 U4.T4 | length 19.9
  Top Layer w0.2: v1(28.7,34.4) U4.T4@29.2,34.9
  MidLayer1 w0.127: v2(13.3,38.6) 17,34.9 24.3,34.9 24.6,34.9 28.2,34.9 v1(28.7,34.4)
  Bottom Layer w0.2: HDR_L1.48@11.2,38.6 v2(13.3,38.6)
EXTEND_B24: HDR_L1.50 U4.U4 | length 20
  Top Layer w0.2: v1(28.7,33.4) U4.U4@29.2,33.9
  MidLayer1 w0.127: v2(12.7,37.8) 13.3,37.8 17.2,33.9 24.3,33.9 24.6,33.9 25.3,33.9 28.2,33.9 v1(28.7,33.4)
  Bottom Layer w0.2: HDR_L1.50@11.2,37.8 v2(12.7,37.8)
EXTEND_B25: HDR_L1.52 U4.U3 | length 18.7
  Top Layer w0.2: v1(27.7,33.4) U4.U3@28.2,33.9
  MidLayer1 w0.127: v2(13.3,37) 16.9,33.4 24.3,33.4 24.6,33.4 25.3,33.4 v1(27.7,33.4)
  Bottom Layer w0.2: HDR_L1.52@11.2,37 v2(13.3,37)
EXTEND_B26: HDR_L1.54 U4.V4 | length 20.4
  Top Layer w0.2: v1(28.7,32.4) U4.V4@29.2,32.9
  MidLayer1 w0.127: v2(12.7,36.2) 13.3,36.2 17.9,31.6 23.5,31.6 23.8,31.9 24.3,31.9 24.6,31.9 28.2,31.9 v1(28.7,32.4)
  Bottom Layer w0.2: HDR_L1.54@11.2,36.2 v2(12.7,36.2)
EXTEND_B27: HDR_L1.56 U4.W3 | length 19.1
  Top Layer w0.2: v1(27.7,31.4) U4.W3@28.2,31.9
  MidLayer1 w0.127: v2(13.3,35.4) 17.6,31.1 23.6,31.1 23.9,31.4 24.3,31.4 24.6,31.4 v1(27.7,31.4)
  Bottom Layer w0.2: HDR_L1.56@11.2,35.4 v2(13.3,35.4)
EXTEND_B28: HDR_L1.58 U4.W4 | length 23.1
  Top Layer w0.2: v1(28.7,31.4) U4.W4@29.2,31.9
  MidLayer1 w0.127: v2(12.7,34.6) 13.4,34.6 17.4,30.6 23.7,30.6 24,30.9 24.3,30.9 24.6,30.9 28.2,30.9 ; 25.3,30.9 28.2,30.9 ; v1(28.7,31.4) 28.2,30.9
  Bottom Layer w0.2: HDR_L1.58@11.2,34.6 v2(12.7,34.6)
EXTEND_B29: HDR_L1.60 U4.U2 | length 16.4
  Top Layer w0.127: v2(13.3,33.8) 20.3,33.8 20.7,33.4 24.3,33.4 24.6,33.4 26.7,33.4 U4.U2@27.2,33.9
  Bottom Layer w0.2: HDR_L1.60@11.2,33.8 v2(13.3,33.8)
EXTEND_B30: HDR_L1.62 U4.V2 | length 16.5
  Top Layer w0.127: v2(12.7,33) 13,32.7 21.3,32.7 21.4,32.8 23.3,32.8 23.7,32.4 24.3,32.4 24.6,32.4 26.7,32.4 U4.V2@27.2,32.9
  Bottom Layer w0.2: HDR_L1.62@11.2,33 v2(12.7,33)
EXTEND_B31: HDR_L1.64 U4.W1 | length 15.4
  Top Layer w0.127: v2(13.3,32.2) 21.3,32.2 21.9,31.6 23.4,31.6 23.7,31.9 24.3,31.9 24.6,31.9 U4.W1@26.2,31.9
  Bottom Layer w0.2: HDR_L1.64@11.2,32.2 v2(13.3,32.2)
EXTEND_B32: HDR_L1.66 U4.W2 | length 16.4
  Top Layer w0.127: v2(12.7,31.4) 21.5,31.4 21.7,31.2 23.6,31.2 23.8,31.4 24.3,31.4 24.6,31.4 26.7,31.4 U4.W2@27.2,31.9
  Bottom Layer w0.2: HDR_L1.66@11.2,31.4 v2(12.7,31.4)
EXTEND_B33: HDR_L1.68 U4.Y1 | length 15.1
  Top Layer w0.127: v2(13.3,30.6) 22.7,30.6 23,30.9 24.3,30.9 24.6,30.9 U4.Y1@26.2,30.9
  Bottom Layer w0.2: HDR_L1.68@11.2,30.6 v2(13.3,30.6)
EXTEND_B34: HDR_L1.70 U4.Y2 | length 16.5
  Top Layer w0.127: v2(12.7,29.8) 20,29.8 20.1,29.9 24.3,29.9 24.6,29.9 25.3,29.9 25.8,30.4 26.7,30.4 U4.Y2@27.2,30.9
  Bottom Layer w0.2: HDR_L1.70@11.2,29.8 v2(12.7,29.8)
EXTEND_B35: HDR_L1.72 U4.AA1 | length 15.4
  Top Layer w0.127: v2(13.3,29) 20.2,29 20.7,29.5 24.3,29.5 24.6,29.5 25.3,29.5 25.7,29.9 U4.AA1@26.2,29.9
  Bottom Layer w0.2: HDR_L1.72@11.2,29 v2(13.3,29)
EXTEND_B36: HDR_L1.74 U4.AB1 | length 15.5
  Top Layer w0.127: v2(12.7,28.2) 19.8,28.2 20.7,29.1 23.4,29.1 23.7,28.8 24.3,28.8 24.6,28.8 26.1,28.8 U4.AB1@26.2,28.9
  Bottom Layer w0.2: HDR_L1.74@11.2,28.2 v2(12.7,28.2)
EXTEND_B37: HDR_L1.76 U4.AB2 | length 17
  Top Layer w0.127: v2(13.3,27.4) 19.4,27.4 20.8,28.8 23.3,28.8 23.7,28.4 24.3,28.4 24.6,28.4 25.7,28.4 26.7,28.4 U4.AB2@27.2,28.9
  Bottom Layer w0.2: HDR_L1.76@11.2,27.4 v2(13.3,27.4)
EXTEND_B38: HDR_L1.78 U4.AC1 | length 15.5
  Top Layer w0.127: v2(12.7,26.6) 20.3,26.6 20.7,27 22.7,27 23.6,27.9 24.3,27.9 24.6,27.9 U4.AC1@26.2,27.9
  Bottom Layer w0.2: HDR_L1.78@11.2,26.6 v2(12.7,26.6)
EXTEND_B39: HDR_L1.80 U4.AC2 | length 16.9
  Top Layer w0.127: v2(13.3,25.8) 19.9,25.8 20.7,26.6 22.7,26.6 23.5,27.4 24.3,27.4 24.6,27.4 26.7,27.4 U4.AC2@27.2,27.9
  Bottom Layer w0.2: HDR_L1.80@11.2,25.8 v2(13.3,25.8)
EXTEND_B40: HDR_L1.82 U4.AD1 | length 16
  Top Layer w0.127: v2(12.7,25) 19.5,25 20.7,26.2 22.9,26.2 23.8,27.1 24.3,27.1 24.6,27.1 25.5,27.1 25.7,26.9 U4.AD1@26.2,26.9
  Bottom Layer w0.2: HDR_L1.82@11.2,25 v2(12.7,25)
EXTEND_B41: HDR_L1.84 U4.AD2 | length 17.1
  Top Layer w0.127: v2(13.3,24.2) 19.3,24.2 20.7,25.6 24.3,25.6 24.6,25.6 25.1,25.6 25.9,26.4 26.7,26.4 U4.AD2@27.2,26.9
  Bottom Layer w0.2: HDR_L1.84@11.2,24.2 v2(13.3,24.2)
EXTEND_B42: HDR_L1.86 U4.Y4 | length 21.3
  Top Layer w0.2: v1(28.7,30.4) U4.Y4@29.2,30.9
  MidLayer1 w0.127: v2(12.7,23.4) 15.2,23.4 21.3,29.5 24.3,29.5 24.6,29.5 25.2,29.5 25.8,30.1 27.3,30.1 27.5,29.9 28.2,29.9 v1(28.7,30.4)
  Bottom Layer w0.2: HDR_L1.86@11.2,23.4 v2(12.7,23.4)
EXTEND_B43: HDR_L1.88 U4.M6 | length 33.4
  Top Layer w0.2: v1(30.7,39.4) U4.M6@31.2,38.9
  MidLayer3 w0.127: v2(13.3,22.6) 14.3,23.6 14.3,33.6 20.6,39.9 24.3,39.9 24.6,39.9 26.4,39.9 30.2,39.9 v1(30.7,39.4)
  Bottom Layer w0.2: HDR_L1.88@11.2,22.6 v2(13.3,22.6)
EXTEND_B44: HDR_L1.90 U4.P6 | length 31.5
  Top Layer w0.2: v1(30.7,36.4) U4.P6@31.2,36.9
  MidLayer3 w0.127: v2(12.7,21.8) 13.3,21.8 14.9,23.4 14.9,32.4 18.4,35.9 24.3,35.9 24.6,35.9 30.2,35.9 v1(30.7,36.4)
  Bottom Layer w0.2: HDR_L1.90@11.2,21.8 v2(12.7,21.8)
EXTEND_B45: HDR_L1.92 U4.T6 | length 31
  Top Layer w0.2: v1(30.7,34.4) U4.T6@31.2,34.9
  MidLayer3 w0.127: v2(13.3,21) 13.3,21.2 15.5,23.4 15.5,32.1 17.3,33.9 24.3,33.9 24.6,33.9 30.2,33.9 v1(30.7,34.4)
  Bottom Layer w0.2: HDR_L1.92@11.2,21 v2(13.3,21)
EXTEND_B46: HDR_L1.94 U4.U6 | length 32.3
  Top Layer w0.2: v1(30.7,33.4) U4.U6@31.2,33.9
  MidLayer3 w0.127: v2(12.7,20.2) 13.6,20.2 14,19.8 14.9,19.8 16.1,21 16.1,31.8 17.2,32.9 24.3,32.9 24.6,32.9 30.2,32.9 v1(30.7,33.4)
  Bottom Layer w0.2: HDR_L1.94@11.2,20.2 v2(12.7,20.2)
EXTEND_B47: HDR_L1.96 U4.V6 | length 29.7
  Top Layer w0.2: v1(30.7,32.4) U4.V6@31.2,32.9
  MidLayer3 w0.127: v2(13.3,19.4) 16.9,19.4 18.6,21.1 18.6,28.1 22.1,31.6 23.6,31.6 23.9,31.9 24.3,31.9 24.6,31.9 30.2,31.9 v1(30.7,32.4)
  Bottom Layer w0.2: HDR_L1.96@11.2,19.4 v2(13.3,19.4)
EXTEND_B48: HDR_L1.98 U4.W6 | length 29.7
  Top Layer w0.2: v1(30.7,31.4) U4.W6@31.2,31.9
  MidLayer3 w0.127: v2(12.7,18.6) 17.2,18.6 19.2,20.6 19.2,27.8 22.3,30.9 24.3,30.9 24.6,30.9 30.2,30.9 v1(30.7,31.4)
  Bottom Layer w0.2: HDR_L1.98@11.2,18.6 v2(12.7,18.6)
EXTEND_B49: HDR_L1.100 U4.Y6 | length 29.6
  Top Layer w0.2: v1(30.7,30.4) U4.Y6@31.2,30.9
  MidLayer3 w0.127: v2(13.3,17.8) 17.2,17.8 19.8,20.4 19.8,27.5 22.2,29.9 24.3,29.9 24.6,29.9 30.2,29.9 v1(30.7,30.4)
  Bottom Layer w0.2: HDR_L1.100@11.2,17.8 v2(13.3,17.8)
EXTEND_C0: HDR_T1.89 U4.N20 | length 37.8
  Top Layer w0.178: U4.N20@45.2,37.9 v1(45.7,38.4)
  MidLayer4 w0.127: v1@45.75,38.4 46.2,38.9 52.8,38.9 53.1,38.9 56.218,38.9 59.918,42.6 61.3,42.6 63.154,44.454 63.154,46.664 62.608,47.21 62.608,54.597 63.7,55.689 v2(63.7,57.9)
  Bottom Layer w0.2: v2(63.7,57.9) HDR_T1.89@63.7,59.4 v2(63.7,57.9)
EXTEND_C1: HDR_T1.87 U4.M20 | length 35.3
  Top Layer w0.178: U4.M20@45.2,38.9 v1(45.7,39.4)
  MidLayer4 w0.127: v1(45.7,39.4) 46.2,39.9 52.8,39.9 53.1,39.9 56.859,39.9 59.859,42.9 61.2,42.9 62.9,44.6 62.9,46.559 62.354,47.105 62.354,54.826 62.9,55.372 v2(62.9,57.3)
  Bottom Layer w0.2: v2(62.9,57.3) HDR_T1.87@62.9,59.4
EXTEND_C2: HDR_T1.85 U4.L20 | length 34.3
  Top Layer w0.178: U4.L20@45.2,39.9 v1(45.7,40.4)
  MidLayer4 w0.127: v1(45.7,40.4) 46.1,40.9 50,40.9 52.8,40.9 53.1,40.9 57.5,40.9 60,43.4 61.3,43.4 62.6,44.7 62.6,46.5 62.1,47 v2(62.1,57.9)
  Bottom Layer w0.2: v2(62.1,57.9) HDR_T1.85@62.1,59.4
EXTEND_C3: HDR_T1.83 U4.K20 | length 31.8
  Top Layer w0.178: U4.K20@45.2,40.9 v1(45.7,41.4)
  MidLayer4 w0.127: v1(45.7,41.4) 46.2,41.9 52.8,41.9 53.1,41.9 57.5,41.9 60.879,45.279 61.3,45.7 v2(61.3,57.3)
  Bottom Layer w0.2: v2(61.3,57.3) HDR_T1.83@61.3,59.4
EXTEND_C4: HDR_T1.81 U4.N21 | length 32.3
  Top Layer w0.2: U4.N21@46.2,37.9 v1(46.7,38.4)
  MidLayer3 w0.127: v1(46.7,38.4) 47.2,38.9 52.8,38.9 53.1,38.9 55.5,38.9 57.5,40.9 57.5,51.7 60.5,54.7 v2(60.5,57.9)
  Bottom Layer w0.2: v2(60.5,57.9) HDR_T1.81@60.5,59.4
EXTEND_C5: HDR_T1.79 U4.M21 | length 30.8
  Top Layer w0.2: U4.M21@46.2,38.9 v1(46.7,39.4)
  MidLayer3 w0.127: v1(46.7,39.4) 47.2,39.9 51,39.9 52.8,39.9 53.1,39.9 55.2,39.9 57.2,41.9 57.2,54.8 v2(59.7,57.3)
  Bottom Layer w0.2: v2(59.7,57.3) HDR_T1.79@59.7,59.4
EXTEND_C6: HDR_T1.77 U4.L21 | length 29.7
  Top Layer w0.2: U4.L21@46.2,39.9 v1(46.7,40.4)
  MidLayer3 w0.127: v1(46.7,40.4) 47.2,40.9 52.8,40.9 53.1,40.9 55.7,40.9 56.9,42.1 56.9,55.1 58.9,57.1 v2(58.9,57.9)
  Bottom Layer w0.2: v2(58.9,57.9) HDR_T1.77@58.9,59.4
EXTEND_C7: HDR_T1.75 U4.K21 | length 27.7
  Top Layer w0.2: U4.K21@46.2,40.9 v1(46.7,41.4)
  MidLayer3 w0.127: v1(46.7,41.4) 47.2,41.9 52.8,41.9 53.1,41.9 54.5,41.9 56.6,44 56.6,55.8 v2(58.1,57.3)
  Bottom Layer w0.2: v2(58.1,57.3) HDR_T1.75@58.1,59.4
EXTEND_C8: HDR_T1.73 U4.J21 | length 26.7
  Top Layer w0.2: U4.J21@46.2,41.9 v1(46.7,42.4)
  MidLayer3 w0.127: v1(46.7,42.4) 47.2,42.9 52.8,42.9 53.1,42.9 55,42.9 56.3,44.2 56.3,56.2 57.3,57.2 v2(57.3,57.9)
  Bottom Layer w0.2: v2(57.3,57.9) HDR_T1.73@57.3,59.4
EXTEND_C9: HDR_T1.71 U4.H21 | length 25.6
  Top Layer w0.2: U4.H21@46.2,42.9 v1(46.7,43.4)
  MidLayer3 w0.127: v1(46.7,43.4) 47.2,43.9 52.8,43.9 53.1,43.9 55.5,43.9 56,44.4 56,56.8 v2(56.5,57.3)
  Bottom Layer w0.2: v2(56.5,57.3) HDR_T1.71@56.5,59.4
EXTEND_C10: HDR_T1.69 U4.J20 | length 27.1
  Top Layer w0.2: U4.J20@45.2,41.9 v1(45.7,42.4)
  MidLayer4 w0.127: v1(45.7,42.4) 46.2,42.9 52.8,42.9 53.1,42.9 55.1,42.9 55.7,43.5 v2(55.7,57.9)
  Bottom Layer w0.2: v2(55.7,57.9) HDR_T1.69@55.7,59.4
EXTEND_C11: HDR_T1.67 U4.H20 | length 25.4
  Top Layer w0.2: U4.H20@45.2,42.9 v1(45.7,43.4)
  MidLayer4 w0.127: v1(45.7,43.4) 46.2,43.9 47,43.9 47.2,44.1 47.2,51.5 47.2,51.8 47.2,52.3 47.5,52.6 49.7,52.6 50.1,52.2 54.1,52.2 54.9,53 v2(54.9,57.3)
  Bottom Layer w0.2: v2(54.9,57.3) HDR_T1.67@54.9,59.4
EXTEND_C12: HDR_T1.65 U4.C26 | length 14.8
  Top Layer w0.127: U4.C26@51.2,47.9 52.8,47.9 53.1,47.9 53.9,47.9 54.7,48.7 54.7,55.9 54.1,56.5 v2(54.1,57.9)
  Bottom Layer w0.2: v2(54.1,57.9) HDR_T1.65@54.1,59.4
EXTEND_C13: HDR_T1.63 U4.C25 | length 15.6
  Top Layer w0.127: U4.C25@50.2,47.9 50.7,48.4 52.8,48.4 53.1,48.4 53.9,48.4 54.4,48.9 54.4,53 53.3,54.1 v2(53.3,57.3)
  Bottom Layer w0.2: v2(53.3,57.3) HDR_T1.63@53.3,59.4
EXTEND_C14: HDR_T1.61 U4.D24 | length 17.7
  Top Layer w0.2: U4.D24@49.2,46.9 v1(49.7,47.4)
  MidLayer1 w0.127: v1(49.7,47.4) 50,47.7 52.8,47.7 53.1,47.7 53.8,47.7 54.4,48.3 54.4,53 52.5,54.9 v2(52.5,57.9)
  Bottom Layer w0.2: v2(52.5,57.9) HDR_T1.61@52.5,59.4
EXTEND_C15: HDR_T1.59 U4.B23 | length 11.9
  Top Layer w0.127: U4.B23@48.2,48.9 48.7,49.4 48.7,50.4 49.4,51.1 49.4,51.5 49.4,51.8 49.4,55 v2(51.7,57.3)
  Bottom Layer w0.2: v2(51.7,57.3) HDR_T1.59@51.7,59.4
EXTEND_C16: HDR_T1.57 U4.C24 | length 17.1
  Top Layer w0.2: U4.C24@49.2,47.9 v1(49.7,48.4)
  MidLayer1 w0.127: v1(49.7,48.4) 52.8,48.4 53.1,48.4 53.6,48.4 54,48.8 54,51.1 52.6,52.5 52.6,53.4 50.9,55.1 v2(50.9,57.9)
  Bottom Layer w0.2: v2(50.9,57.9) HDR_T1.57@50.9,59.4
EXTEND_C17: HDR_T1.55 U4.C23 | length 12.3
  Top Layer w0.2: U4.C23@48.2,47.9 v1(48.7,48.4)
  MidLayer1 w0.127: v1(48.7,48.4) 49.1,48.8 49.1,51.5 49.1,51.8 49.1,56.3 v2(50.1,57.3)
  Bottom Layer w0.2: v2(50.1,57.3) HDR_T1.55@50.1,59.4
EXTEND_C18: HDR_T1.53 U4.D22 | length 13.4
  Top Layer w0.2: U4.D22@47.2,46.9 v1(47.7,47.4)
  MidLayer1 w0.127: v1(47.7,47.4) 48.2,47.9 48.2,48.6 48.7,49.1 48.7,51.5 48.7,51.8 48.7,56.7 49.3,57.3 v2(49.3,57.9)
  Bottom Layer w0.2: v2(49.3,57.9) HDR_T1.53@49.3,59.4
EXTEND_C19: HDR_T1.51 U4.C22 | length 12.9
  Top Layer w0.2: U4.C22@47.2,47.9 v1(47.7,48.4)
  MidLayer1 w0.127: v1(47.7,48.4) 47.7,48.7 48.2,49.2 48.2,50 47.2,51 47.2,51.5 47.2,51.8 47.2,56 v2(48.5,57.3)
  Bottom Layer w0.2: v2(48.5,57.3) HDR_T1.51@48.5,59.4
EXTEND_C20: HDR_T1.49 U4.D21 | length 13.5
  Top Layer w0.2: U4.D21@46.2,46.9 v1(46.7,47.4)
  MidLayer1 w0.127: v1(46.7,47.4) 47.2,47.9 47.2,49.8 46.7,50.3 46.7,51.5 46.7,51.8 46.7,56.4 47.7,57.4 v2(47.7,57.9)
  Bottom Layer w0.2: v2(47.7,57.9) HDR_T1.49@47.7,59.4
EXTEND_C21: HDR_T1.47 U4.C21 | length 12.2
  Top Layer w0.2: U4.C21@46.2,47.9 v1(46.7,48.4)
  MidLayer1 w0.127: v1(46.7,48.4) 46.7,49.8 46.2,50.3 46.2,51.5 46.2,51.8 46.2,56.6 v2(46.9,57.3)
  Bottom Layer w0.2: v2(46.9,57.3) HDR_T1.47@46.9,59.4
EXTEND_C22: HDR_T1.45 U4.D20 | length 13.2
  Top Layer w0.2: U4.D20@45.2,46.9 v1(45.7,47.4)
  MidLayer1 w0.127: v1(45.7,47.4) 46.2,47.9 46.2,49.8 45.8,50.2 45.8,51.5 45.8,51.8 45.8,57 46.1,57.3 v2(46.1,57.9)
  Bottom Layer w0.2: v2(46.1,57.9) HDR_T1.45@46.1,59.4
EXTEND_C23: HDR_T1.43 U4.D19 | length 13.3
  Top Layer w0.2: U4.D19@44.2,46.9 v1(44.7,47.4)
  MidLayer1 w0.127: v1(44.7,47.4) 45.2,47.9 45.2,48.7 45.7,49.2 45.7,49.8 45.4,50.1 45.4,51.5 45.4,51.8 45.4,57.2 v2(45.3,57.3)
  Bottom Layer w0.2: v2(45.3,57.3) HDR_T1.43@45.3,59.4
EXTEND_C24: HDR_T1.41 U4.C19 | length 12.2
  Top Layer w0.2: U4.C19@44.2,47.9 v1(44.7,48.4)
  MidLayer1 w0.127: v2(44.5,57.9) 44.5,57.3 45,56.8 45,51.8 45,51.5 45,49.9 45.2,49.7 45.2,49.2 44.7,48.7 v1(44.7,48.4)
  Bottom Layer w0.2: v2(44.5,57.9) HDR_T1.41@44.5,59.4
EXTEND_C25: HDR_T1.39 U4.D18 | length 13.4
  Top Layer w0.2: U4.D18@43.2,46.9 v1(43.7,47.4)
  MidLayer1 w0.127: v1(43.7,47.4) 44.2,47.9 44.2,50.2 43.7,50.7 43.7,51.5 43.7,51.8 43.7,52.5 43.4,52.8 43.4,57 v2(43.7,57.3)
  Bottom Layer w0.2: v2(43.7,57.3) HDR_T1.39@43.7,59.4
EXTEND_C26: HDR_T1.37 U4.C17 | length 11.8
  Top Layer w0.2: U4.C17@42.2,47.9 v1(42.7,48.4)
  MidLayer1 w0.127: v1(42.7,48.4) 42.7,50.8 42.7,51.5 42.7,51.8 42.7,57.2 42.9,57.4 v2(42.9,57.9)
  Bottom Layer w0.2: v2(42.9,57.9) HDR_T1.37@42.9,59.4
EXTEND_C27: HDR_T1.35 U4.D17 | length 13
  Top Layer w0.2: U4.D17@42.2,46.9 v1(42.7,47.4)
  MidLayer1 w0.127: v2(42.1,57.3) 42.2,57.2 42.2,51.8 42.2,51.5 42.2,47.9 v1(42.7,47.4)
  Bottom Layer w0.2: v2(42.1,57.3) HDR_T1.35@42.1,59.4
EXTEND_C28: HDR_T1.33 U4.D16 | length 13
  Top Layer w0.2: U4.D16@41.2,46.9 v1(41.7,47.4)
  MidLayer1 w0.127: v2(41.3,57.9) 41.3,57.2 41.2,57.1 41.2,51.8 41.2,51.5 41.2,47.9 v1(41.7,47.4)
  Bottom Layer w0.2: v2(41.3,57.9) HDR_T1.33@41.3,59.4
EXTEND_C29: HDR_T1.31 U4.C14 | length 14.5
  Top Layer w0.2: U4.C14@39.2,47.9 v1(39.7,48.4)
  MidLayer4 w0.127: v1(39.7,48.4) 37.668,50.432 37.668,55.829 38.176,56.337 39.537,56.337 v2(40.5,57.3)
  Bottom Layer w0.2: v2(40.5,57.3) HDR_T1.31@40.5,59.4
EXTEND_C30: HDR_T1.29 U4.D15 | length 13.1
  Top Layer w0.2: U4.D15@40.2,46.9 v1(40.7,47.4)
  MidLayer1 w0.127: v2(39.7,57.9) 39.7,54.102 40.2,53.602 40.2,47.9 v1(40.7,47.4)
  Bottom Layer w0.2: v2(39.7,57.9) HDR_T1.29@39.7,59.4
EXTEND_C31: HDR_T1.27 U4.D13 | length 13.4
  Top Layer w0.2: v1(37.7,47.4) U4.D13@38.2,46.9
  MidLayer1 w0.127: v1(37.7,47.4) 38.2,47.9 38.2,48.7 38,48.9 38,51.5 38,51.8 38,56.4 v2(38.9,57.3)
  Bottom Layer w0.2: v2(38.9,57.3) HDR_T1.27@38.9,59.4
EXTEND_C32: HDR_T1.25 U4.C13 | length 11.9
  Top Layer w0.2: v1(37.7,48.4) U4.C13@38.2,47.9
  MidLayer1 w0.127: v1(37.7,48.4) 37.7,51.5 37.7,51.8 37.7,57 38.1,57.4 v2(38.1,57.9)
  Bottom Layer w0.2: v2(38.1,57.9) HDR_T1.25@38.1,59.4
EXTEND_C33: HDR_T1.23 U4.C12 | length 12
  Top Layer w0.2: v1(36.7,48.4) U4.C12@37.2,47.9
  MidLayer1 w0.127: v1(36.7,48.4) 37.2,48.9 37.2,51.5 37.2,51.8 37.2,57.2 v2(37.3,57.3)
  Bottom Layer w0.2: v2(37.3,57.3) HDR_T1.23@37.3,59.4
EXTEND_C34: HDR_T1.21 U4.D11 | length 13.4
  Top Layer w0.2: v1(35.7,47.4) U4.D11@36.2,46.9
  MidLayer1 w0.127: v1(35.7,47.4) 36.2,47.9 36.2,51.596 36.9,52.296 36.9,57 36.5,57.4 v2(36.5,57.9)
  Bottom Layer w0.2: v2(36.5,57.9) HDR_T1.21@36.5,59.4
EXTEND_C35: HDR_T1.19 U4.D10 | length 13
  Top Layer w0.2: v1(34.7,47.4) U4.D10@35.2,46.9
  MidLayer1 w0.127: v1(34.7,47.4) 35.2,47.9 35.2,51.5 35.2,51.8 35.2,56.7 v2(35.7,57.2)
  Bottom Layer w0.2: v2@35.7,57.3 HDR_T1.19@35.7,59.4
EXTEND_C36: HDR_T1.17 U4.C10 | length 11.8
  Top Layer w0.2: v1(34.7,48.4) U4.C10@35.2,47.9
  MidLayer1 w0.127: v1(34.7,48.4) 34.7,50.8 34.7,51.5 34.7,51.8 34.7,55.9 34.9,56.1 v2(34.9,57.9)
  Bottom Layer w0.2: v2(34.9,57.9) HDR_T1.17@34.9,59.4
EXTEND_C37: HDR_T1.15 U4.D9 | length 13.3
  Top Layer w0.2: v1(33.7,47.4) U4.D9@34.2,46.9
  MidLayer1 w0.127: v1(33.7,47.4) 33.2,47.9 33.2,48.7 33.7,49.2 33.7,51.5 33.7,51.8 33.7,52.4 34.1,52.8 v2(34.1,57.3)
  Bottom Layer w0.2: v2(34.1,57.3) HDR_T1.15@34.1,59.4
EXTEND_C38: HDR_T1.13 U4.C8 | length 12.2
  Top Layer w0.2: v1(32.7,48.4) U4.C8@33.2,47.9
  MidLayer1 w0.127: v1(32.7,48.4) 32.7,48.7 33.2,49.2 33.2,51.5 33.2,51.8 33.2,52.3 32.9,52.6 32.9,56.7 33.3,57.1 v2(33.3,57.9)
  Bottom Layer w0.2: v2(33.3,57.9) HDR_T1.13@33.3,59.4
EXTEND_C39: HDR_T1.11 U4.D8 | length 13.2
  Top Layer w0.2: v1(32.7,47.4) U4.D8@33.2,46.9
  MidLayer1 w0.127: v2(32.5,57.3) 32.5,51.8 32,51.3 32,48.8 32.2,48.6 32.2,47.9 v1(32.7,47.4)
  Bottom Layer w0.2: v2(32.5,57.3) HDR_T1.11@32.5,59.4
EXTEND_C40: HDR_T1.12 U4.B10 | length 23.9
  Top Layer w0.127: v2(32.5,68.3) 32.5,62.6 36,59.1 36,57.7 36.3,57.4 36.3,57 35.5,56.2 35.5,53.1 34.7,52.3 34.7,51.8 34.7,51.5 34.7,49.4 U4.B10@35.2,48.9
  Bottom Layer w0.2: HDR_T1.12@32.5,66.2 v2(32.5,68.3)
EXTEND_C41: HDR_T1.9 U4.C7 | length 12
  Top Layer w0.2: v1(31.7,48.4) U4.C7@32.2,47.9
  MidLayer1 w0.127: v1(31.7,48.4) 31.7,51.4 32.1,51.8 32.1,56.4 31.7,56.8 v2(31.7,57.9)
  Bottom Layer w0.2: v2(31.7,57.9) HDR_T1.9@31.7,59.4
EXTEND_C42: HDR_T1.10 U4.A9 | length 21.3
  Top Layer w0.127: v2(31.7,67.7) 31.7,62.8 35.4,59.1 35.4,57.7 35.2,57.5 35.2,53.2 34.2,52.2 34.2,51.8 34.2,51.5 U4.A9@34.2,49.9
  Bottom Layer w0.2: HDR_T1.10@31.7,66.2 v2(31.7,67.7)
EXTEND_C43: HDR_T1.7 U4.D7 | length 13.3
  Top Layer w0.2: v1(31.7,47.4) U4.D7@32.2,46.9
  MidLayer1 w0.127: v2@30.8,57.2 v2(30.9,57.3) 30.9,56.6 30.8,56.5 30.8,49.5 31.2,49.1 31.2,47.9 v1(31.7,47.4)
  Bottom Layer w0.2: v2(30.9,57.3) HDR_T1.7@30.9,59.4
EXTEND_C44: HDR_T1.8 U4.B9 | length 23.7
  Top Layer w0.127: v2(30.9,68.3) 30.9,62.6 34.4,59.1 34.4,57.7 34.7,57.4 34.7,53.1 33.7,52.1 33.7,51.8 33.7,51.5 33.7,49.4 U4.B9@34.2,48.9
  Bottom Layer w0.2: HDR_T1.8@30.9,66.2 v2(30.9,68.3)
EXTEND_C45: HDR_T1.5 U4.C6 | length 12
  Top Layer w0.2: v1(30.7,48.4) U4.C6@31.2,47.9
  MidLayer1 w0.127: v2(30.1,57.9) 30.1,56.6 30.5,56.2 30.5,49.3 30.7,49.1 v1(30.7,48.4)
  Bottom Layer w0.2: v2(30.1,57.9) HDR_T1.5@30.1,59.4
EXTEND_C46: HDR_T1.6 U4.A8 | length 23.1
  Top Layer w0.127: v2(30.1,67.7) 30.1,62.8 33.8,59.1 33.8,57.7 33.5,57.4 33.5,56 34.1,55.4 34.1,52.9 33.2,52 33.2,51.8 33.2,51.5 U4.A8@33.2,49.9
  Bottom Layer w0.2: HDR_T1.6@30.1,66.2 v2(30.1,67.7) HDR_T1.6@30.1,66.2
EXTEND_C47: HDR_T1.3 U4.D6 | length 13.3
  Top Layer w0.2: v1(30.7,47.4) U4.D6@31.2,46.9
  MidLayer1 w0.127: v2(29.3,57.3) 29.3,56.8 30.2,55.9 30.2,52 30.2,51.3 30.2,47.9 v1(30.7,47.4)
  Bottom Layer w0.2: v2(29.3,57.3) HDR_T1.3@29.3,59.4
EXTEND_C48: HDR_T1.4 U4.A7 | length 23.9
  Top Layer w0.127: v2(29.3,68.3) 29.3,62.6 32.8,59.1 32.8,57.7 33.1,57.4 33.1,55.8 32.9,55.6 32.2,54.9 32.2,51.8 32.2,51.5 U4.A7@32.2,49.9
  Bottom Layer w0.2: 29.3,67.7 HDR_T1.4@29.3,66.2 v2(29.3,68.3)
EXTEND_C49: HDR_T1.2 U4.B7 | length 22.2
  Top Layer w0.127: v2(28.5,67.7) 28.5,62.8 32.2,59.1 32.2,57.7 31.9,57.4 31.9,51.2 31.7,51 31.7,49.4 U4.B7@32.2,48.9
  Bottom Layer w0.2: HDR_T1.2@28.5,66.2 v2(28.5,67.7)
FB: R24.2 R25.1 U5.8 | length 3.1
  Top Layer w0.2: U5.8@72.2,45.9 U5.8@72.2,45.929
  Top Layer w0.3: R24.2@71.338,47.4 72.1,47.4 ; U5.8@72.1,45.9 72.1,45.929 72.1,47.4 ; R25.1@72.862,47.4 72.1,47.4
FPGA_CCLK: HDR_T1.66 R17.1 | length 54.5
  MidLayer3 w0.127: v2(54.1,67.7) 53.2,67.7 52.8,68.1 52.8,68.6 53.4,69.2 62.9,69.2 64.2,67.9 64.2,57.7 63.7,57.2 63.7,55.9 58.654,50.854 58.654,39.554 v1(57.7,38.6)
  Bottom Layer w0.127: R17.1@52.451,40.688 53.112,40.688 53.4,40.4 53.4,39.6 53.6,39.4 57.4,39.4 57.7,39.1 v1(57.7,38.6)
  Bottom Layer w0.2: HDR_T1.66@54.1,66.2 v2(54.1,67.7)
FPGA_CLK: HDR_B1.2 U4.AE14 | length 23.5
  Top Layer w0.127: U4.AE14@39.2,25.9 39.7,25.4 39.7,22.2 39.9,22 v1(39.9,19.1)
  MidLayer1 w0.127: v2(28.5,16.9) 29.4,16 39.5,16 40.2,16.7 40.2,17.1 40,17.3 40,18.575 39.9,18.675 v1(39.9,19.1)
  Bottom Layer w0.2: HDR_B1.2@28.5,15.4 v2(28.5,16.9)
FPGA_CLK1: HDR_T1.90 U4.C15 | length 59.8
  Top Layer w0.2: U4.C15@40.2,47.9 v1(40.7,48.4)
  MidLayer4 w0.127: v1(37.6,71) 41.1,71 42.1,70 42.1,58 39.954,55.855 38.355,55.855 38.1,55.6 38.1,51 v1(40.7,48.4)
  Bottom Layer w0.127: v1(37.6,71) 57.4,71 59.1,69.3 62,69.3 63.7,67.6 HDR_T1.90@63.7,66.2
FPGA_DIN: HDR_T1.64 U4.G12 | length 41
  Top Layer w0.203: U4.G12@37.2,43.9 v1(37.7,44.4)
  MidLayer1 w0.127: v1(37.7,44.4) 38.5,45.2 38.5,48.768 38.254,49.014 38.254,54.078 38.43,54.254 38.917,54.254 39.4,54.737 39.4,57.5 39.2,57.7 39.2,58.306 39.494,58.6 51.683,58.6 53.3,60.216 v1(53.3,68.3)
  Bottom Layer w0.203: HDR_T1.64@53.3,66.2 v1(53.3,68.3)
FPGA_DONE: HDR_T1.74 NT2.2 R11.1 R16.1 | length 101.7
  MidLayer2 w0.127: v1(55.2,22.8) 54.2,21.8 54.2,17.5 59.5,12.2 59.5,6.9 v1(58.9,6.3)
  MidLayer3 w0.127: v1(37.3,6.3) 37.6,6.6 58.6,6.6 v1(58.9,6.3)
  MidLayer4 w0.127: v2(57.3,67.7) 57.3,58.8 58.7,57.4 58.7,47.2 v1(59.7,46.2)
  Bottom Layer w0.127: NT2.2@36.6,6.575 37.025,6.575 v1(37.3,6.3) ; R16.1@52.451,42.938 52.451,45.951 52.7,46.2 v1(59.7,46.2) 59.7,44.2 58.55,43.05 58.55,38.35 56.8,36.6 56.8,25.7 55.538,24.438 R11.1@55.538,23.5 ; v1(55.2,22.8) 55.538,23.138 R11.1@55.538,23.5 ; R11.1@55.5,23.5 R11.1@55.538,23.5
  Bottom Layer w0.2: HDR_T1.74@57.3,66.2 v2(57.3,67.7)
FPGA_ID0: HDR_T1.42 NT3.1
FPGA_ID1: HDR_T1.40 NT5.1
FPGA_ID2: HDR_T1.38 NT6.1
FPGA_ID3: HDR_T1.36 NT7.1
FPGA_INIT: HDR_T1.68 R8.1 U4.G15 | length 49.6
  Top Layer w0.203: U4.G15@40.2,43.9 v1(40.7,44.4)
  MidLayer1 w0.203: v1(48.7,76.2) 48.7,74.5 v1(54.9,68.3)
  MidLayer2 w0.127: v1(40.7,44.4) 41.2,44.9 41.2,45.8 41.3,45.9 50.2,45.9 55.4,51.1 55.4,57.5 55.1,57.8 55.1,67.3 54.9,67.5 v1(54.9,68.3)
  Bottom Layer w0.203: R8.1@47.738,76.2 v1(48.7,76.2) ; HDR_T1.68@54.9,66.2 v1(54.9,68.3)
FPGA_INSTALLED: HDR_T1.34 NT1.1 | length 1.4
  Bottom Layer w0.2: HDR_T1.34@41.3,66.2 NT1.1@41.3,67.6
FPGA_M0: HDR_T1.60 R14.1 | length 81.2
  Bottom Layer w0.127: R14.1@21.962,22.4 20.9,22.4 20.7,22.6 20.7,46.9 20.3,47.3 20.3,55.3 21.4,56.4 26.4,56.4 26.9,56.9 26.9,68.1 28.4,69.6 51,69.6 51.8,68.8 51.8,68 51.7,67.9 HDR_T1.60@51.7,66.2
FPGA_M1: HDR_T1.58 R13.1 | length 76
  Bottom Layer w0.127: R13.1@21.962,24.6 21.5,24.6 21.3,24.8 21.3,47.1 20.9,47.5 20.9,55.1 21.6,55.8 26.8,55.8 27.5,56.5 27.5,67.7 28.8,69 50.3,69 50.6,68.7 50.6,68 50.9,67.7 HDR_T1.58@50.9,66.2
FPGA_M2: HDR_T1.56 R12.1 | length 79.6
  Top Layer w0.127: v2(50.1,68.4) v2(51.2,68.4)
  Bottom Layer w0.127: R12.1@21.962,23.5 21.155,23.5 21,23.655 21,47 20.6,47.4 20.6,55.2 21.5,56.1 26.6,56.1 27.2,56.7 27.2,67.9 28.6,69.3 50.8,69.3 51.2,68.9 v2(51.2,68.4) ; HDR_T1.56@50.1,66.2 v2@50.1,68.3
FPGA_PROG_CLK: HDR_T1.88
FPGA_PROG_PWR_ON: HDR_T1.86 R4.1 | length 54.5
  Top Layer w0.127: v1(24.7,55.3) 24.7,55.9 v1(24.7,56.9)
  Bottom Layer w0.127: R4.1@24.462,54.5 24.5,54.538 24.5,55.1 v1(24.7,55.3) ; v1(24.7,56.9) 25.6,57.8 25.6,58.1 26,58.5 26,68.4 28.1,70.5 57.3,70.5 58.9,68.9 61.4,68.9 62.1,68.2 HDR_T1.86@62.1,66.2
